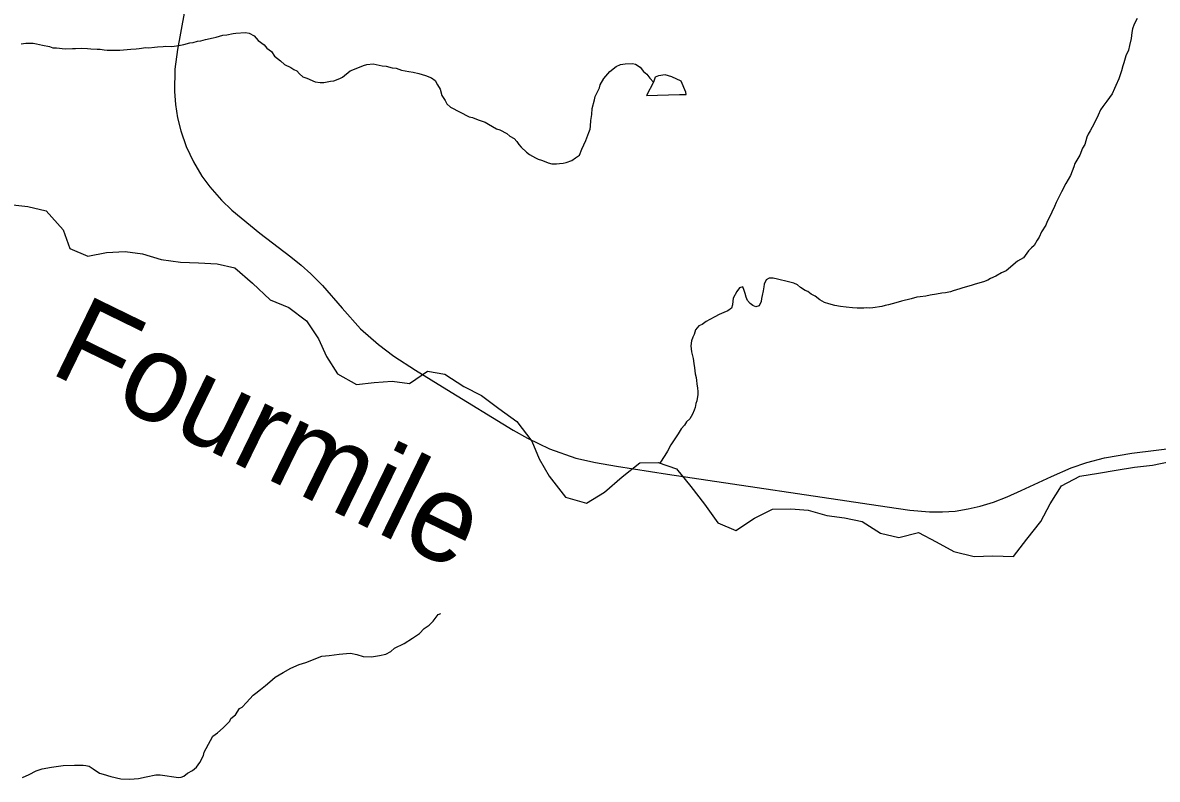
# Model space of a CAD drawing. Extents: x 1310247 to 1664935, y 235267 to 584339.
# Drawn here: x 1496305 to 1502798, y 386844 to 391172 of the extents above; entities that cross this region are included whole.
import ezdxf

# ---------------------------------------------------------------- set-up
doc = ezdxf.new("R2010")
doc.units = 0
for name, color, linetype in [('GM_X_Minor_Lake', 7, 'Continuous'), ('GM_X_Minor_River', 7, 'Continuous'), ('GM_X_Minor_River_Text', 7, 'Continuous'), ('GM_X_Rail_Line', 7, 'Continuous')]:
    doc.layers.add(name, color=color, linetype=linetype)

msp = doc.modelspace()

# ---------------------------------------------------------------- linework, layer by layer
at = {"layer": 'GM_X_Minor_Lake'}
for points in [[(1499915.1, 390832), (1499874.7, 390755.1), (1500063.6, 390761.8), (1500101.7, 390761.2), (1500099.9, 390775.3), (1500072.9, 390837.9), (1500019.1, 390862.9)], [(1500019.1, 390862.9), (1499981.2, 390873.6), (1499942.9, 390868.2), (1499924.7, 390860.5), (1499915.1, 390832)]]:
    msp.add_lwpolyline(points, dxfattribs=at)
at = {"layer": 'GM_X_Minor_River'}
for points in [[(1502683.3, 391196.8), (1502664.7, 391163), (1502656.2, 391137.1), (1502651.9, 391115.1), (1502647.3, 391081.1), (1502638.6, 391041.1), (1502632.1, 391015.1), (1502617.5, 390983.3), (1502606.8, 390943.3), (1502600.5, 390925.4), (1502592, 390897.4), (1502577.2, 390851.5), (1502560.5, 390813.7), (1502552.2, 390795.8), (1502539.6, 390765.9), (1502508.8, 390722.3), (1502486.2, 390692.6), (1502471.8, 390672.8), (1502459.3, 390642.9), (1502436.4, 390595.1), (1502413.6, 390553.4), (1502401.2, 390533.6), (1502394.9, 390517.6), (1502382.2, 390475.7), (1502369.8, 390453.8), (1502355.1, 390414)], [(1496295.5, 391051.9), (1496321.7, 391055.5), (1496363.8, 391054.7), (1496383.8, 391050.4), (1496417.8, 391043.8), (1496457.8, 391035), (1496477.8, 391028.7), (1496497.9, 391028.3), (1496548, 391023.4), (1496590.1, 391024.7), (1496606.2, 391024.4), (1496638.3, 391025.8), (1496674.5, 391025.2), (1496694.5, 391022.8), (1496730.6, 391020.2), (1496748.6, 391019.9), (1496770.7, 391017.5), (1496788.7, 391015.2), (1496844.9, 391014.2), (1496861, 391015.9), (1496923.3, 391020.8), (1496953.4, 391022.3), (1496971.5, 391024), (1497009.8, 391029.4), (1497025.8, 391029.1), (1497058, 391032.5), (1497076.1, 391034.2), (1497108.2, 391035.7), (1497124.3, 391037.4), (1497158.4, 391036.8), (1497184.6, 391040.4), (1497206.7, 391044), (1497226.9, 391047.6), (1497261.1, 391057.1), (1497279.2, 391058.8), (1497305.5, 391066.3), (1497323.6, 391068), (1497349.8, 391075.6), (1497394.1, 391084.8), (1497412.2, 391088.5), (1497450.5, 391099.9), (1497472.7, 391103.5), (1497508.9, 391110.9), (1497525, 391112.6), (1497579.3, 391115.7), (1497601.3, 391111.3), (1497629.2, 391096.8), (1497652.8, 391070.3), (1497686.5, 391045.6), (1497702.3, 391027.3)], [(1497702.3, 391027.3), (1497728, 391006.8), (1497745.6, 390980.3), (1497779.3, 390953.7), (1497803.1, 390933.2), (1497838.9, 390916.5), (1497856.8, 390904.1), (1497872.7, 390895.8), (1497888.5, 390879.5), (1497908.3, 390863.1), (1497930.2, 390854.7), (1497978, 390833.8), (1498006.1, 390829.3), (1498028.2, 390830.9), (1498066.4, 390838.3), (1498084.5, 390840), (1498118.9, 390853.4), (1498135.1, 390861.1), (1498177.8, 390896.5), (1498204.1, 390906.1), (1498254.6, 390927.3), (1498274.8, 390932.9), (1498311, 390936.3), (1498361, 390925.4), (1498385, 390923), (1498419, 390914.4), (1498441, 390912), (1498473, 390901.4), (1498515, 390892.6), (1498539, 390888.2), (1498571, 390881.6), (1498609, 390870.9), (1498644.9, 390856.2), (1498664.7, 390841.8), (1498678.3, 390817.5), (1498694, 390791.1), (1498703.4, 390754.8), (1498723, 390726.4), (1498732.7, 390708.2), (1498752.5, 390689.8), (1498859.9, 390633.7), (1498877.9, 390629.4), (1498911.8, 390616.8), (1498927.8, 390610.4), (1498951.8, 390604), (1498969.6, 390591.6), (1499015.3, 390564.8), (1499035.3, 390558.4), (1499075.1, 390537.6), (1499092.9, 390523.3), (1499116.8, 390508.8), (1499132.6, 390492.5), (1499144.3, 390476.2), (1499158.1, 390459.9), (1499187.8, 390431.3), (1499205.6, 390418.9), (1499239.4, 390398.3), (1499255.3, 390392), (1499273.3, 390385.6), (1499289.3, 390379.3), (1499311.2, 390370.9), (1499333.2, 390364.5), (1499359.3, 390364.1), (1499377.4, 390365.8), (1499397.5, 390369.4), (1499415.6, 390373.1), (1499447.9, 390384.6), (1499468.2, 390398.3), (1499490.6, 390414), (1499505.2, 390447.8), (1499528.1, 390497.6), (1499544.9, 390543.5), (1499551.3, 390563.4), (1499553.6, 390579.4), (1499556.1, 390613.5), (1499560.7, 390647.5), (1499563.3, 390681.6), (1499576.2, 390731.5), (1499580.5, 390749.5), (1499605.4, 390799.3), (1499609.7, 390817.2), (1499630.4, 390853), (1499665.2, 390892.5), (1499701.8, 390922), (1499726.1, 390933.6), (1499752.3, 390937.1), (1499794.4, 390938.4), (1499812.4, 390934.1), (1499838.3, 390917.6), (1499857.9, 390893.2), (1499875.7, 390876.8), (1499893.4, 390854.4), (1499915.1, 390832)], [(1502355.1, 390414), (1502326.2, 390366.3), (1502319.8, 390348.4), (1502300.9, 390298.5), (1502274.1, 390252.8), (1502249.2, 390205.1), (1502228.4, 390163.3), (1502218.1, 390143.5), (1502209.7, 390121.5), (1502195, 390087.7), (1502178.5, 390055.9), (1502168, 390034), (1502159.7, 390014), (1502135, 389976.3), (1502122.4, 389944.5), (1502110.1, 389928.6), (1502093.5, 389896.8), (1502077.2, 389885), (1502060.9, 389867.3), (1502032.1, 389827.6), (1501997.6, 389808.2), (1501932.5, 389753.1), (1501906.2, 389741.5), (1501873.8, 389722), (1501843.4, 389708.5), (1501827.2, 389698.8), (1501802.9, 389689.2), (1501782.8, 389683.5), (1501750.5, 389674), (1501732.3, 389668.3), (1501683.9, 389655.1), (1501667.8, 389649.4), (1501629.5, 389638), (1501613.3, 389632.3), (1501585.1, 389626.8), (1501565, 389625.1), (1501534.8, 389619.6), (1501498.6, 389614.2), (1501472.4, 389608.6), (1501440.2, 389603.2), (1501422.1, 389601.5), (1501389.8, 389592), (1501333.4, 389579), (1501301.1, 389569.5), (1501258.8, 389558.2), (1501240.6, 389554.5), (1501220.5, 389548.8), (1501170.2, 389541.7), (1501152.1, 389540), (1501134, 389540.3), (1501117.9, 389538.6), (1501101.9, 389538.9), (1501079.8, 389539.3), (1501053.7, 389541.7), (1501017.6, 389544.4), (1500985.6, 389548.9), (1500951.6, 389553.5), (1500917.6, 389564.2), (1500893.6, 389570.6), (1500865.8, 389587.1), (1500840.1, 389607.7), (1500816.2, 389620.1), (1500798.3, 389634.5), (1500782.4, 389640.8), (1500756.6, 389657.3), (1500738.8, 389671.7), (1500716.8, 389682.1), (1500664.9, 389695), (1500646.9, 389699.4), (1500624.9, 389705.8), (1500598.9, 389710.2), (1500576.8, 389710.6), (1500558.6, 389700.9), (1500548.1, 389677), (1500545.9, 389661), (1500541.5, 389639), (1500537, 389611), (1500532.7, 389595), (1500530.4, 389577), (1500520, 389553.1), (1500499.8, 389547.4), (1500483.8, 389553.7), (1500468, 389566), (1500452.2, 389582.3), (1500444.5, 389602.6), (1500438.8, 389622.7), (1500433.1, 389640.9), (1500425.4, 389661.1), (1500407.3, 389655.4), (1500390.8, 389633.6), (1500370.1, 389595.8), (1500367.9, 389579.8), (1500367.5, 389557.7), (1500361.2, 389539.8), (1500340.8, 389524.1), (1500316.6, 389514.5), (1500290.3, 389502.9), (1500266, 389489.3), (1500237.6, 389473.7), (1500215.3, 389462.1), (1500193, 389446.4)], [(1496231, 390131.9), (1496333.2, 390119.8), (1496439.5, 390095.8), (1496535.7, 389987.5), (1496573.8, 389881.2), (1496678.1, 389837), (1496784.4, 389857.1), (1496890.6, 389863.1), (1496990.9, 389849.1), (1497097.1, 389817), (1497207.4, 389802.9), (1497309.7, 389798.9), (1497417.9, 389792.9), (1497518.2, 389768.9), (1497620.5, 389682.6), (1497720.7, 389586.3), (1497827, 389542.2), (1497929.2, 389466), (1497997.4, 389363.7), (1498043.5, 389263.4), (1498105.7, 389163.2), (1498214, 389103), (1498316.2, 389113), (1498418.5, 389121), (1498518.7, 389109), (1498621, 389179.2), (1498721.2, 389161.2), (1498829.5, 389091), (1498929.8, 389038.8), (1499030, 388964.6), (1499132.3, 388890.4), (1499218.5, 388778.1), (1499260.6, 388677.8), (1499316.8, 388577.5), (1499411, 388457.2), (1499531.3, 388423.1), (1499633.6, 388487.3), (1499735.8, 388573.5), (1499836.1, 388653.8), (1499940.3, 388655.8), (1500046.6, 388619.7), (1500128.8, 388519.4), (1500207, 388417.1), (1500283.2, 388310.8), (1500385.5, 388266.7), (1500491.7, 388336.9), (1500596, 388389), (1500700.2, 388391), (1500800.5, 388383), (1500906.8, 388353), (1501007, 388338.9), (1501109.3, 388318.9), (1501213.5, 388252.7), (1501317.8, 388226.6), (1501430.1, 388256.7), (1501532.3, 388202.5), (1501632.6, 388146.4), (1501748.9, 388118.3), (1501857.2, 388122.3), (1501975.5, 388118.3), (1502051.6, 388218.6), (1502131.8, 388318.9), (1502184, 388419.2), (1502250.1, 388523.5), (1502354.4, 388577.6), (1502460.6, 388595.7), (1502562.9, 388611.8), (1502667.2, 388629.8), (1502769.4, 388641.8), (1502871.7, 388661.9)], [(1500193, 389446.4), (1500174.8, 389438.7), (1500154.3, 389415), (1500147.9, 389389), (1500139.6, 389373.1), (1500131.2, 389353.1), (1500128.7, 389323.1), (1500132.1, 389288.9), (1500137.8, 389266.8), (1500141.5, 389250.6), (1500145.1, 389222.5), (1500148.7, 389198.3), (1500150.4, 389180.2), (1500152.1, 389164.1), (1500157.8, 389142), (1500161.5, 389125.8), (1500163.2, 389105.7), (1500166.8, 389081.6), (1500168.5, 389061.5), (1500168.2, 389045.5), (1500161.6, 389009.4), (1500157.3, 388993.5), (1500152.9, 388971.5), (1500146.6, 388955.5), (1500138.2, 388933.6), (1500121.7, 388905.8), (1500103.3, 388888), (1500091, 388870.2), (1500072.6, 388848.4), (1500056, 388820.6), (1500037.5, 388790.8), (1500025.2, 388775), (1500012.8, 388757.1), (1499994.1, 388721.3), (1499979.7, 388695.5), (1499951.1, 388652.1)], [(1497560.7, 387256.4), (1497585.3, 387284), (1497624.1, 387325.5), (1497638.3, 387337.3), (1497664.8, 387356.9), (1497693.3, 387380.5), (1497719.7, 387402.1), (1497750.3, 387427.7), (1497794.9, 387455), (1497839.5, 387480.3), (1497886, 387501.6), (1497924.3, 387513), (1498017.3, 387547.5), (1498057.5, 387552.8), (1498115.8, 387559.8), (1498158, 387563.1), (1498180.1, 387564.7), (1498216.2, 387558.1), (1498252.1, 387547.4), (1498300.3, 387544.6), (1498346.5, 387551.8), (1498382.8, 387559.2), (1498411.2, 387574.8), (1498431.6, 387594.5), (1498488.2, 387621.6), (1498534.9, 387650.9), (1498575.5, 387678.3), (1498602.1, 387705.9), (1498630.5, 387725.5), (1498653, 387749.2), (1498681.7, 387786.8), (1498697.9, 387792.6)], [(1496303.4, 386854.7), (1496341.8, 386872.1), (1496382.3, 386891.5), (1496416.6, 386903), (1496469, 386914.1), (1496535.4, 386923), (1496601.7, 386925.8), (1496649.8, 386925), (1496665.8, 386922.7), (1496685.8, 386918.3), (1496707.7, 386903.9), (1496743.4, 386879.2), (1496765.4, 386872.8), (1496809.3, 386860), (1496865.3, 386846.9), (1496917.4, 386844), (1496967.7, 386849.2), (1497012, 386858.4), (1497066.4, 386869.5), (1497090.5, 386869.1), (1497118.6, 386866.6), (1497168.6, 386857.7), (1497196.7, 386855.2), (1497210.7, 386857), (1497226.9, 386862.7), (1497247.2, 386878.4), (1497275.6, 386894), (1497300, 386913.6), (1497318.5, 386939.4), (1497339.3, 386979.2), (1497343.6, 386999.2), (1497354, 387021.1), (1497393.3, 387090.7), (1497419.7, 387110.3), (1497452.3, 387137.8), (1497489.1, 387177.3), (1497495.4, 387191.3), (1497521.8, 387212.9), (1497544.5, 387248.6), (1497560.7, 387256.4)]]:
    msp.add_lwpolyline(points, dxfattribs=at)
at = {"layer": 'GM_X_Rail_Line'}
msp.add_lwpolyline([(1497266.2, 391435.8), (1497190.9, 391019.5), (1497175.5, 390905.7), (1497172.7, 390778.1), (1497178.2, 390705), (1497190.9, 390628), (1497209, 390553.2), (1497239.2, 390464.1), (1497281.6, 390375.6), (1497330, 390294.8), (1497375.1, 390233.2), (1497441.6, 390157.3), (1497501, 390099.6), (1497662.4, 389967.8), (1497839.2, 389833.4), (1497899.1, 389784.5), (1497953.2, 389735.8), (1498019.5, 389669.5), (1498133.4, 389539), (1498237.9, 389421.5), (1498340.1, 389330.3), (1498428.7, 389264.3), (1498552.4, 389185.1), (1498732.2, 389073.5), (1499112.2, 388841.4), (1499192.5, 388796.3), (1499319.9, 388733.9), (1499470, 388680.8), (1499581.8, 388656.6), (1499702.8, 388634.6), (1499995.3, 388589), (1501252.5, 388401.8), (1501380.5, 388384.4), (1501494.3, 388374), (1501569.1, 388374), (1501640.6, 388378.4), (1501715.4, 388390.5), (1501784.7, 388406.4), (1501859.5, 388429.5), (1501939.2, 388459.8), (1502017.9, 388495.8), (1502192.2, 388575.8), (1502305.4, 388626.4), (1502395.1, 388656.6), (1502495.2, 388683), (1502651, 388708.8), (1502914.7, 388742.4)], dxfattribs=at)

# ---------------------------------------------------------------- texts
at = {"layer": 'GM_X_Minor_River_Text'}
msp.add_text('Fourmile', height=499.96, rotation=334.01169, dxfattribs=at).set_placement((1496448, 389173.4))

doc.saveas('drawing.dxf')
